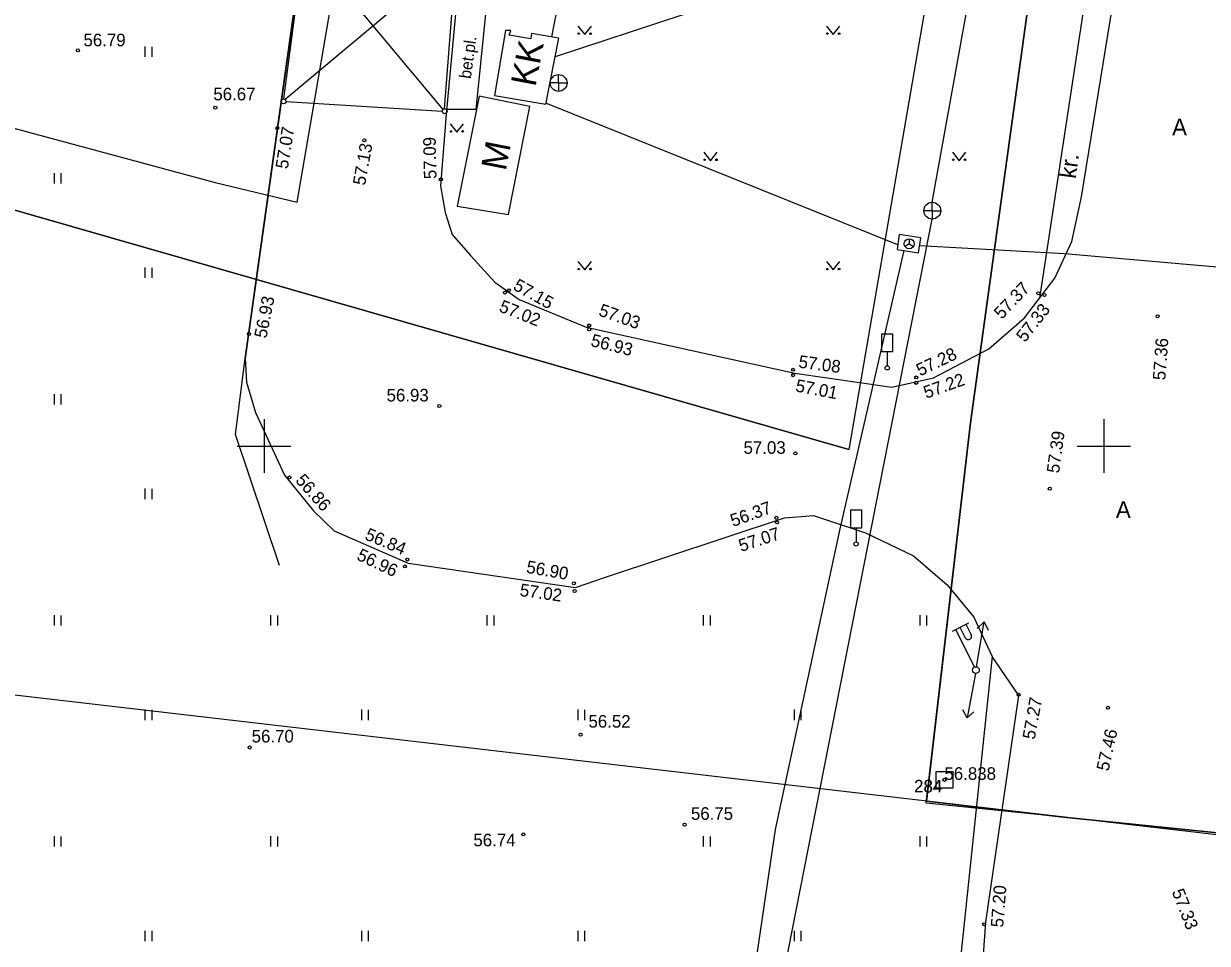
# Model space of a CAD drawing. Extents: x 9156 to 9809, y 2728 to 4000.
# Drawn here: x 9335.7 to 9406.2, y 3770.4 to 3825.1 of the extents above; entities that cross this region are included whole.
import ezdxf

# ---------------------------------------------------------------- set-up
doc = ezdxf.new("R2010")
doc.units = 0
for name, color, linetype in [('Level 11', 7, 'Continuous'), ('Level 54', 7, 'Continuous'), ('Level 58', 7, 'Continuous'), ('Level 6', 7, 'Continuous'), ('Level 60', 7, 'Continuous'), ('Level 7', 7, 'Continuous')]:
    doc.layers.add(name, color=color, linetype=linetype)

# ---------------------------------------------------------------- blocks, each defined once
blk = doc.blocks.new('KKOL')
at = {"layer": 'Level 58'}
for p, q in [((0, 1.59349), (0, -1.5935)), ((-1.5935, 0), (1.59349, 0))]:
    blk.add_line(p, q, dxfattribs=at)
blk = doc.blocks.new('VPP')
at = {"layer": 'Level 60'}
blk.add_lwpolyline([(-0.5, 0.5), (0.5, 0.5), (0.5, -0.5), (-0.5, -0.5)], close=True, dxfattribs=at)
blk.add_circle((0, 0), 0.0923, dxfattribs=at)

msp = doc.modelspace()

# ---------------------------------------------------------------- linework, layer by layer
at = {"layer": 'Level 11'}
msp.add_lwpolyline([(9307.157, 3935.863), (9316.851, 3823.838), (9347.087, 3815.684), (9351.98, 3814.51), (9364.444, 3887.037), (9370.906, 3923.994)], close=True, dxfattribs=at)
msp.add_lwpolyline([(9307.157, 3935.863), (9316.851, 3823.838), (9347.087, 3815.684), (9351.98, 3814.51), (9364.444, 3887.037), (9370.906, 3923.994)], close=True, dxfattribs=at)
at = {"layer": 'Level 54'}
for p, q in [((9389.783, 3814.502), (9394.668, 3841.535)), ((9348.879, 3805.216), (9352.324, 3829.753)), ((9352.365, 3829.772), (9351.161, 3820.655)), ((9352.469, 3829.815), (9360.648, 3820.025)), ((9368.166, 3829.7), (9367.115, 3824.341)), ((9361.336, 3829.056), (9351.266, 3820.611)), ((9360.753, 3820.069), (9361.44, 3829.013)), ((9363.529, 3829.023), (9362.601, 3820.024)), ((9398.854, 3826.385), (9396.165, 3808.8)), ((9398.675, 3814.833), (9400.53, 3826.264)), ((9364.378, 3824.716), (9363.725, 3820.855)), ((9364.688, 3824.716), (9364.378, 3824.716)), ((9364.585, 3824.441), (9364.688, 3824.716)), ((9365.891, 3824.234), (9364.585, 3824.441)), ((9365.925, 3824.544), (9365.891, 3824.234)), ((9367.541, 3824.268), (9365.925, 3824.544)), ((9368.689, 3824.987), (9369.09, 3824.483)), ((9369.09, 3824.483), (9369.489, 3824.987)), ((9383.487, 3824.987), (9383.888, 3824.483)), ((9383.888, 3824.483), (9384.287, 3824.987)), ((9342.912, 3823.77), (9342.912, 3823.15)), ((9343.317, 3823.759), (9343.317, 3823.15)), ((9366.785, 3820.338), (9367.541, 3824.268)), ((9367.538, 3821.602), (9367.038, 3821.602)), ((9367.538, 3821.602), (9367.538, 3822.102)), ((9367.538, 3821.602), (9368.038, 3821.602)), ((9367.538, 3821.602), (9367.538, 3821.102)), ((9362.807, 3820.817), (9361.501, 3814.266)), ((9365.833, 3820.197), (9362.807, 3820.817)), ((9363.725, 3820.855), (9366.785, 3820.338)), ((9351.309, 3820.507), (9360.605, 3819.921)), ((9364.561, 3813.784), (9365.833, 3820.197)), ((9362.601, 3820.024), (9360.917, 3820.024)), ((9361.074, 3819.17), (9361.477, 3818.665)), ((9361.477, 3818.665), (9361.874, 3819.17)), ((9376.187, 3817.481), (9376.588, 3816.978)), ((9376.588, 3816.978), (9376.987, 3817.481)), ((9390.986, 3817.481), (9391.386, 3816.978)), ((9391.386, 3816.978), (9391.786, 3817.481)), ((9337.506, 3816.239), (9337.506, 3815.619)), ((9337.912, 3816.227), (9337.912, 3815.619)), ((9389.783, 3814.002), (9389.783, 3814.502)), ((9398.09, 3812.179), (9398.675, 3814.833)), ((9361.501, 3814.266), (9364.561, 3813.784)), ((9389.783, 3814.002), (9389.283, 3814.002)), ((9389.783, 3814.002), (9390.283, 3814.002)), ((9389.783, 3814.002), (9389.783, 3813.502)), ((9380.945, 3768.645), (9389.783, 3813.502)), ((9388.412, 3812.337), (9388.412, 3812.037)), ((9388.412, 3812.037), (9388.162, 3811.871)), ((9388.412, 3812.037), (9388.412, 3812.037)), ((9388.412, 3812.037), (9388.662, 3811.871)), ((9388.425, 3812.072), (9388.425, 3812.072)), ((9397.07, 3809.982), (9398.09, 3812.179)), ((9368.689, 3810.978), (9369.09, 3810.474)), ((9369.09, 3810.474), (9369.489, 3810.978)), ((9383.487, 3810.978), (9383.888, 3810.474)), ((9383.888, 3810.474), (9384.287, 3810.978)), ((9342.912, 3810.619), (9342.912, 3809.998)), ((9343.317, 3810.607), (9343.317, 3809.998)), ((9397.427, 3809.317), (9397.427, 3809.317)), ((9394.977, 3807.46), (9394.977, 3807.46)), ((9393.503, 3806.036), (9393.503, 3806.036)), ((9387.102, 3805.603), (9387.102, 3804.779)), ((9392.671, 3805.442), (9392.671, 3805.442)), ((9392.671, 3805.442), (9392.671, 3805.442)), ((9348.307, 3800.694), (9348.879, 3805.216)), ((9381.842, 3804.766), (9381.842, 3804.766)), ((9390.78, 3804.643), (9390.78, 3804.643)), ((9391.72, 3805.003), (9391.72, 3805.003)), ((9386.808, 3804.107), (9386.808, 3804.107)), ((9387.774, 3803.999), (9387.774, 3803.999)), ((9388.782, 3804.086), (9388.782, 3804.086)), ((9388.799, 3804.053), (9388.799, 3804.053)), ((9389.839, 3804.256), (9389.839, 3804.256)), ((9337.506, 3803.087), (9337.506, 3802.467)), ((9337.912, 3803.076), (9337.912, 3802.467)), ((9350, 3801.25), (9350, 3798.75)), ((9400, 3801.25), (9400, 3798.75)), ((9350.92, 3792.901), (9348.307, 3800.694)), ((9348.75, 3800), (9351.25, 3800)), ((9398.75, 3800), (9401.25, 3800)), ((9342.912, 3797.467), (9342.912, 3796.847)), ((9343.317, 3797.456), (9343.317, 3796.847)), ((9380.535, 3796.133), (9380.535, 3796.133)), ((9383.551, 3795.543), (9383.551, 3795.543)), ((9383.75, 3795.456), (9383.75, 3795.456)), ((9385.246, 3795.121), (9385.246, 3794.297)), ((9387.222, 3794.218), (9387.222, 3794.218)), ((9387.238, 3794.224), (9387.238, 3794.224)), ((9388.141, 3793.761), (9388.141, 3793.761)), ((9389.97, 3792.693), (9389.97, 3792.693)), ((9390.689, 3791.991), (9390.689, 3791.991)), ((9391.365, 3791.16), (9391.365, 3791.16)), ((9391.665, 3790.713), (9391.665, 3790.713)), ((9337.506, 3789.936), (9337.506, 3789.316)), ((9337.912, 3789.925), (9337.912, 3789.316)), ((9350.388, 3789.936), (9350.388, 3789.316)), ((9350.793, 3789.925), (9350.793, 3789.316)), ((9363.269, 3789.936), (9363.269, 3789.316)), ((9363.675, 3789.925), (9363.675, 3789.316)), ((9376.151, 3789.936), (9376.151, 3789.316)), ((9376.557, 3789.925), (9376.557, 3789.316)), ((9389.033, 3789.936), (9389.033, 3789.316)), ((9389.438, 3789.925), (9389.438, 3789.316)), ((9390.986, 3788.99), (9391.967, 3789.487)), ((9391.165, 3789.08), (9392.294, 3786.85)), ((9391.432, 3789.216), (9391.748, 3788.591)), ((9391.789, 3789.396), (9392.105, 3788.772)), ((9392.407, 3789.47), (9392.407, 3789.47)), ((9392.408, 3789.464), (9392.408, 3789.464)), ((9392.417, 3786.868), (9392.863, 3789.531)), ((9392.464, 3789.153), (9392.863, 3789.531)), ((9392.863, 3789.531), (9393.117, 3789.043)), ((9392.54, 3789.024), (9392.54, 3789.024)), ((9392.54, 3789.024), (9392.54, 3789.024)), ((9393.637, 3787.564), (9393.637, 3787.564)), ((9392.348, 3786.475), (9391.857, 3783.82)), ((9393.266, 3786.144), (9393.266, 3786.144)), ((9342.912, 3784.316), (9342.912, 3783.696)), ((9343.317, 3784.305), (9343.317, 3783.696)), ((9355.793, 3784.316), (9355.793, 3783.696)), ((9356.199, 3784.305), (9356.199, 3783.696)), ((9368.675, 3784.316), (9368.675, 3783.696)), ((9369.081, 3784.305), (9369.081, 3783.696)), ((9381.557, 3784.316), (9381.557, 3783.696)), ((9381.962, 3784.305), (9381.962, 3783.696)), ((9391.857, 3783.82), (9391.611, 3784.312)), ((9392.262, 3784.191), (9391.857, 3783.82)), ((9392.47, 3779.809), (9392.47, 3779.809)), ((9337.506, 3776.785), (9337.506, 3776.165)), ((9337.912, 3776.774), (9337.912, 3776.165)), ((9350.388, 3776.785), (9350.388, 3776.165)), ((9350.793, 3776.774), (9350.793, 3776.165)), ((9376.151, 3776.785), (9376.151, 3776.165)), ((9376.557, 3776.774), (9376.557, 3776.165)), ((9389.033, 3776.785), (9389.033, 3776.165)), ((9389.438, 3776.774), (9389.438, 3776.165)), ((9342.912, 3771.165), (9342.912, 3770.545)), ((9343.317, 3771.153), (9343.317, 3770.545)), ((9355.793, 3771.165), (9355.793, 3770.545)), ((9356.199, 3771.153), (9356.199, 3770.545)), ((9368.675, 3771.165), (9368.675, 3770.545)), ((9369.081, 3771.153), (9369.081, 3770.545)), ((9381.557, 3771.165), (9381.557, 3770.545)), ((9381.962, 3771.153), (9381.962, 3770.545))]:
    msp.add_line(p, q, dxfattribs=at)
for points in [[(9362.363, 3836.166), (9360.85, 3819.754), (9360.506, 3815.479), (9360.781, 3813.893), (9361.194, 3812.583), (9362.294, 3811.342), (9363.738, 3809.756), (9365.182, 3808.721), (9369.17, 3807.066), (9381.6, 3804.327), (9387.375, 3803.5), (9389.851, 3804.052), (9393.151, 3805.776), (9395.282, 3807.637), (9397.07, 3809.982)], [(9367.358, 3823.183), (9374.959, 3825.685), (9388.635, 3832.224), (9399.107, 3832.855)], [(9352.324, 3829.753), (9348.879, 3805.216), (9348.949, 3803.791), (9349.499, 3801.998), (9351.218, 3798.274), (9352.937, 3796.137), (9354.174, 3794.964), (9358.575, 3793.034), (9368.545, 3791.585), (9370.332, 3792.206), (9380.99, 3795.723), (9382.709, 3795.861), (9385.803, 3794.826), (9388.675, 3793.468), (9390.669, 3791.744), (9392.25, 3789.813), (9393.35, 3787.469)], [(9387.725, 3811.971), (9366.785, 3820.402)], [(9388.093, 3811.627), (9384.276, 3795.068), (9380.436, 3777.191), (9377.873, 3759.795), (9375.78, 3736.18)], [(9449.477, 3808.39), (9432.322, 3809.209), (9412.866, 3810.111), (9397.661, 3811.43), (9389.031, 3811.914)], [(9393.35, 3787.469), (9390.607, 3761.393), (9389.609, 3750)], [(9391.155, 3750), (9392.427, 3764.251), (9392.975, 3771.674), (9394.934, 3785.155), (9393.35, 3787.469)]]:
    msp.add_lwpolyline(points, dxfattribs=at)
for points in [[(9389.1, 3812.391), (9387.813, 3812.577), (9387.684, 3811.686), (9388.971, 3811.5)], [(9386.786, 3806.68), (9387.419, 3806.68), (9387.419, 3805.603), (9386.786, 3805.603)], [(9384.929, 3796.198), (9385.562, 3796.198), (9385.562, 3795.121), (9384.929, 3795.121)], [(9390.009, 3780.638), (9391.009, 3780.638), (9391.009, 3779.638), (9390.009, 3779.638)]]:
    msp.add_lwpolyline(points, close=True, dxfattribs=at)
for centre, radius in [((9368.739, 3824.537), 0.0407), ((9369.439, 3824.537), 0.0486), ((9383.537, 3824.537), 0.0407), ((9384.237, 3824.537), 0.0486), ((9338.917, 3823.54), 0.0909), ((9367.538, 3821.602), 0.5), ((9347.1, 3820.133), 0.0909), ((9351.161, 3820.507), 0.148), ((9360.753, 3819.921), 0.148), ((9350.785, 3818.917), 0.0909), ((9361.124, 3818.72), 0.0428), ((9361.824, 3818.72), 0.0452), ((9355.973, 3818.187), 0.0909), ((9376.237, 3817.031), 0.0433), ((9376.937, 3817.031), 0.0482), ((9391.036, 3817.031), 0.0433), ((9391.736, 3817.031), 0.0482), ((9360.525, 3815.859), 0.0909), ((9389.783, 3814.002), 0.5), ((9388.412, 3812.037), 0.3), ((9368.739, 3810.528), 0.0407), ((9369.439, 3810.528), 0.0486), ((9383.537, 3810.528), 0.0407), ((9384.237, 3810.528), 0.0486), ((9364.349, 3809.132), 0.0909), ((9364.577, 3809.269), 0.0909), ((9396.098, 3809.081), 0.0909), ((9396.462, 3808.989), 0.0909), ((9403.195, 3807.718), 0.0909), ((9349.102, 3806.668), 0.0909), ((9369.356, 3807.17), 0.0909), ((9369.356, 3806.941), 0.0909), ((9381.498, 3804.537), 0.0909), ((9387.102, 3804.652), 0.126), ((9381.498, 3804.217), 0.0909), ((9388.826, 3804.08), 0.0909), ((9388.826, 3803.761), 0.0909), ((9360.435, 3802.377), 0.0909), ((9381.634, 3799.561), 0.0909), ((9351.514, 3798.132), 0.0909), ((9396.777, 3797.461), 0.0909), ((9380.496, 3795.727), 0.0909), ((9380.542, 3795.453), 0.0909), ((9385.246, 3794.171), 0.126), ((9358.524, 3793.247), 0.0909), ((9358.387, 3792.837), 0.0909), ((9368.446, 3791.832), 0.0909), ((9368.491, 3791.376), 0.0909), ((9392.384, 3786.671), 0.2), ((9394.919, 3785.203), 0.0909), ((9400.244, 3784.427), 0.0909), ((9368.847, 3782.826), 0.0909), ((9349.146, 3782.064), 0.0909), ((9390.509, 3780.138), 0.0923), ((9375.042, 3777.469), 0.0909), ((9365.433, 3776.891), 0.0909), ((9392.871, 3771.547), 0.0909)]:
    msp.add_circle(centre, radius, dxfattribs=at)
msp.add_arc((9391.927, 3788.681), 0.2, 206.78909, 26.91049, dxfattribs=at)
at = {"layer": 'Level 6'}
msp.add_line((9389.441, 3778.868), (9397.586, 3777.922), dxfattribs=at)
msp.add_lwpolyline([(9406.335, 3871.284), (9417.264, 3870.77), (9419.931, 3861.081), (9410.086, 3776.653), (9389.428, 3778.75), (9392.066, 3801.386), (9401.769, 3871.605)], close=True, dxfattribs=at)
for points in [[(9401.769, 3871.605), (9392.066, 3801.386), (9389.441, 3778.868)], [(9397.586, 3777.922), (9410.086, 3776.653), (9418.608, 3850.018)]]:
    msp.add_lwpolyline(points, dxfattribs=at)
at = {"layer": 'Level 7'}
for p, q in [((9406.13, 3923.27), (9384.82, 3799.8)), ((9397.252, 3871.834), (9384.82, 3799.8)), ((9308.72, 3821.62), (9384.82, 3799.8)), ((9384.82, 3799.8), (9308.72, 3821.62)), ((9453.674, 3771.409), (9312.256, 3787.831))]:
    msp.add_line(p, q, dxfattribs=at)

# ---------------------------------------------------------------- block references
at = {"layer": 'Level 54'}
for name, p in [('KKOL', (9350, 3800)), ('KKOL', (9400, 3800)), ('VPP', (9390.509, 3780.138))]:
    msp.add_blockref(name, p, dxfattribs=at)

# ---------------------------------------------------------------- texts
for s, height, p in [('56.79', 0.75, (9339.251, 3823.782)), ('56.67', 0.75, (9346.982, 3820.567)), ('A', 1, (9404.059, 3818.477)), ('56.93', 0.75, (9357.295, 3802.651)), ('57.03', 0.75, (9378.547, 3799.535)), ('A', 1, (9400.712, 3795.719)), ('56.52', 0.75, (9369.316, 3783.245)), ('56.70', 0.75, (9349.263, 3782.362)), ('56.838', 0.75, (9390.509, 3780.138)), ('56.838', 0.75, (9390.509, 3780.138)), ('284', 0.75, (9388.696, 3779.388)), ('284', 0.75, (9388.708, 3779.388)), ('56.75', 0.75, (9375.414, 3777.76)), ('56.74', 0.75, (9362.464, 3776.184))]:
    msp.add_text(s, height=height, dxfattribs=at).set_placement(p)
for s, height, rotation, p in [('bet.pl.', 0.7, 82.03953, (9362.306, 3821.822)), ('KK', 1.5, 79.14522, (9366.156, 3821.329)), ('57.07', 0.75, 80.80223, (9351.412, 3816.451)), ('57.13', 0.75, 79.88324, (9356.016, 3815.473)), ('57.09', 0.75, 91.16271, (9360.27, 3815.887)), ('M', 1.5, 79.00159, (9364.386, 3816.325)), ('kr.', 1, 82.27036, (9398.323, 3815.873)), ('57.15', 0.75, 330.72565, (9364.774, 3809.342)), ('57.37', 0.75, 46.55056, (9393.922, 3807.499)), ('56.93', 0.75, 78.72207, (9350.141, 3806.375)), ('57.02', 0.75, 338.49644, (9363.936, 3808.024)), ('57.03', 0.75, 340.50852, (9369.866, 3807.781)), ('57.33', 0.75, 51.95619, (9395.302, 3806.127)), ('56.93', 0.75, 345.92489, (9369.406, 3805.959)), ('57.36', 0.75, 85.72273, (9403.655, 3803.897)), ('57.08', 0.75, 352.42278, (9381.789, 3804.668)), ('57.28', 0.75, 25.62382, (9389.058, 3804.134)), ('57.01', 0.75, 349.25779, (9381.603, 3803.25)), ('57.22', 0.75, 19.70594, (9389.426, 3802.81)), ('57.39', 0.75, 82.20679, (9397.33, 3798.353)), ('56.86', 0.75, 311.64709, (9351.827, 3797.927)), ('56.37', 0.75, 19.79462, (9377.923, 3795.181)), ('56.84', 0.75, 337.32171, (9355.947, 3794.463)), ('57.07', 0.75, 18.29362, (9378.403, 3793.693)), ('56.96', 0.75, 334.6351, (9355.466, 3793.264)), ('56.90', 0.75, 350.08175, (9365.576, 3792.464)), ('57.02', 0.75, 352.13216, (9365.195, 3791.08)), ('57.27', 0.75, 79.72384, (9395.883, 3782.503)), ('57.46', 0.75, 77.23145, (9400.272, 3780.618)), ('57.20', 0.75, 85.63784, (9394.008, 3771.339)), ('57.33', 0.75, 291.3488, (9404.033, 3773.485))]:
    msp.add_text(s, height=height, rotation=rotation, dxfattribs=at).set_placement(p)

doc.saveas('drawing.dxf')
